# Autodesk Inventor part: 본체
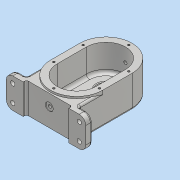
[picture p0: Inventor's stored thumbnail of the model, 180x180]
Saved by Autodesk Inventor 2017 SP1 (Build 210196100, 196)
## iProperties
Part Number: 본체
Material: 알루미늄 6061
Document SubType Name: Modeling
Designer: MRC
Density: 2.7 g/cm^3
Appearance: 알루미늄 - 평지
Mass: 756.449 g
Surface Area: 582.679 cm^2
Volume: 280.166 cm^3
Author: MRC
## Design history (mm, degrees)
sketch "스케치4"
  geometry: L1 (0, 0)-(0, -87); L2 (-40, 0)-(-40, -82); L3 (40, -82)-(40, 0); L4 (-40, -82)-(-61, -82); L5 (-61, -82)-(-61, -92); L6 (-61, -92)-(-35, -92); L7 (-35, -92)-(-35, -87); L8 (-35, -87)-(35, -87); L9 (35, -87)-(35, -92); L10 (35, -92)-(61, -92); L11 (61, -92)-(61, -82); L12 (61, -82)-(40, -82); A1 r 40 centre (0, 0) between (40, 0) and (-40, 0); 1 further point
  constraints: 26 end point, 7 perpendicular, 3 point on line, 2 midpoint, 2 point on circle, 2 tangent, 2 vertical, 1 centre point, 1 horizontal, 1 parallel
  dimensions: "d17" = 40 radius of A1; "d18" = 10 distance of L10.end L11.end; "d19" = 70 distance of L7.end L8.end; "d20" = 122 distance between parallel lines of L5 L11; "d21" = 61 distance from line of point (0, -43.5) L5; "d22" = 92 distance from line of L10 L1.start; "d23" = 5 distance of L8.end L9.end
extrude "돌출4" new body sketch "스케치4" distance "d24" = 46; taper "d25" = 0 deg
sketch "스케치5"
  geometry: L1 (0, 0)-(0, -45); L2 (-40, 0)-(-40, -45); L3 (40, -45)-(40, 0); A1 r 40 centre (0, 0) between (40, 0) and (-40, 0) reference; A2 r 40 centre (0, 0) between (40, 0) and (-40, 0); A3 r 40 centre (0, -45) between (-40, -45) and (40, -45); 1 further point
  constraints: 8 end point, 4 point on circle, 4 tangent, 2 centre point, 1 concentric, 1 midpoint, 1 parallel, 1 vertical
  dimensions: "d26" = 45 distance of L1.start L1.end
extrude "돌출5" join sketch "스케치5" distance "d27" = 3; taper "d28" = 0 deg
sketch "스케치6"
  geometry: L1 (0, 0)-(0, -45); L2 (-26, 0)-(-26, -45); L3 (26, -45)-(26, 0); A1 r 40 centre (0, 0) between (40, 0) and (-40, 0) reference; A2 r 26 centre (0, 0) between (26, 0) and (-26, 0); A3 r 26 centre (0, -45) between (-26, -45) and (26, -45); 1 further point
  constraints: 8 end point, 4 point on circle, 4 tangent, 2 centre point, 1 midpoint, 1 parallel, 1 vertical
  dimensions: "d29" = 26 radius of A2; "d30" = 45 distance of L1.start L1.end
extrude "돌출6" join sketch "스케치6" distance "d31" = 11; taper "d32" = 0 deg
sketch "스케치7"
  geometry: L1 (26, -45)-(26, 0) reference; L2 (-26, -45)-(-26, 0) reference; L3 (-26, -30)-(26, -30); A1 r 26 centre (0, 0) between (26, 0) and (-26, 0) reference
  constraints: 2 end point, 2 point on line, 1 perpendicular
  dimensions: "d33" = 30 distance from line of L3 A1.centre
extrude "돌출7" cut sketch "스케치7" distance "d34" = 3; taper "d35" = 0 deg
sketch "스케치8"
  geometry: L1 (0, 0)-(0, -45); L2 (-30, 0)-(-30, -45); L3 (30, -45)-(30, 0); A1 r 40 centre (0, -45) between (-40, -45) and (40, -45) reference; A2 r 40 centre (0, 0) between (40, 0) and (-40, 0) reference; A3 r 30 centre (0, 0) between (30, 0) and (-30, 0); A4 r 30 centre (0, -45) between (-30, -45) and (30, -45); 1 further point
  constraints: 8 end point, 4 point on circle, 4 tangent, 2 centre point, 1 midpoint, 1 parallel, 1 vertical
  dimensions: "d36" = 30 radius of A3
extrude "돌출8" cut sketch "스케치8" distance "d37" = 41; taper "d38" = 0 deg
hole "구멍1" diameter "d41" = 20; stored, may be unused: countersink angle "d45" = 90 deg, drill point angle "d47" = 0 deg; dims "d39" = 10, "d40" = 10, "d42" = 6, "d43" = 28, "d44" = 8, "d46" = 12
hole "구멍2" diameter "d50" = 22; stored, may be unused: countersink angle "d54" = 90 deg, drill point angle "d56" = 0 deg; dims "d48" = 10, "d49" = 10, "d51" = 6, "d52" = 28, "d53" = 8, "d55" = 100
sketch "스케치9"
  geometry: C1 r 11 at (0, 0) reference; C2 r 14 at (0, 0); A1 r 26 centre (0, 0) between (26, 0) and (-26, 0) reference
  constraints: 1 centre point, 1 coincident
  dimensions: "d57" = 28 diameter of C2
extrude "돌출9" cut sketch "스케치9" distance "d58" = 4; taper "d59" = 0 deg
fillet "모깎기4" dims "d60" = 10, "d61" = 5
sketch "스케치10"
  geometry: L1 (-101, 36)-(-101, 10) reference; L2 (-80, 0)-(-91, 0) reference; L3 (-80, 46)-(-80, 0) reference; L4 (-80, 46)-(-91, 46) reference; A1 r 10 centre (11, 36) between (21, 36) and (11, 46) reference; A2 r 10 centre (11, 10) between (11, 0) and (21, 10) reference; A3 r 10 centre (-91, 36) between (-91, 46) and (-101, 36) reference; A4 r 10 centre (-91, 10) between (-101, 10) and (-91, 0) reference; 1 further point
hole "구멍3" sketch "스케치10" at (-91, 10), (11, 36), (11, 10), (-91, 36) diameter "d62" = 6.6; stored, may be unused: countersink angle "d66" = 90 deg, drill point angle "d68" = 0 deg; dims "d63" = 6, "d64" = 11, "d65" = 2, "d67" = 10
node "작업 평면1"
sketch "스케치11"
  geometry: L1 (75, 49)-(-5, 49) reference; C1 r 6 at (35, 28); 1 further point
  constraints: 1 centre point, 1 vertical alignment
  dimensions: "d70" = 12 diameter of C1; "d71" = 21 distance from line of L1 C1.centre
extrude "돌출10" join sketch "스케치11" stored distance "d72" = 4; taper "d73" = 0 deg
hole "구멍4" diameter "d76" = 4.917; stored, may be unused: countersink angle "d80" = 90 deg, drill point angle "d82" = 0 deg; dims "d74" = 10, "d75" = 10, "d77" = 12, "d78" = 11, "d79" = 2, "d81" = 17.1
sketch "스케치12"
  geometry: L1 (0, 0)-(70, 0) reference; L2 (75, 49)-(-5, 49) reference; 3 further points
  constraints: 1 midpoint, 1 vertical alignment
  dimensions: "d83" = 21 distance from line of point (35, 28) L2
hole "구멍5" sketch "스케치12" at (35, 28) diameter "d84" = 4.917; stored, may be unused: countersink angle "d88" = 90 deg, drill point angle "d90" = 0 deg; dims "d85" = 12, "d86" = 12, "d87" = 1, "d89" = 17.1
sketch "스케치13"
  geometry: C1 r 14 at (0, 0) reference; 1 further point
  constraints: 1 vertical alignment
  dimensions: "d91" = 20 distance of C1.centre point (0, 20)
hole "구멍6" sketch "스케치13" at (0, 20) diameter "d92" = 3.242; stored, may be unused: countersink angle "d96" = 90 deg, drill point angle "d98" = 118 deg; dims "d93" = 8, "d94" = 12, "d95" = 1, "d97" = 10
sketch "스케치14"
  geometry: A1 r 30 centre (0, 0) between (30, 0) and (-30, 0) reference; 1 further point
  constraints: 1 vertical alignment
  dimensions: "d102" = 35 distance of A1.centre point (0, 35)
hole "구멍7" sketch "스케치14" at (0, 35) diameter "d103" = 3.242; stored, may be unused: countersink angle "d107" = 90 deg, drill point angle "d109" = 118 deg; dims "d104" = 8, "d105" = 12, "d106" = 1, "d108" = 10
sketch "스케치15"
  geometry: L1 (0, 0)-(0, -45); L2 (-35, 0)-(-35, -45); L3 (35, -45)-(35, 0); A1 r 40 centre (0, -45) between (-40, -45) and (40, -45) reference; A2 r 40 centre (0, 0) between (40, 0) and (-40, 0) reference; A3 r 35 centre (0, 0) between (35, 0) and (-35, 0); A4 r 35 centre (0, -45) between (-35, -45) and (35, -45); 6 further points
  constraints: 8 end point, 5 point on circle, 4 coincident, 4 tangent, 2 centre point, 1 midpoint, 1 parallel, 1 vertical
  dimensions: "d110" = 70 diameter of A4
hole "구멍8" sketch "스케치15" at (-35, 0), (35, 0), (35, -45), (-35, -45), (0, -80) diameter "d111" = 3.242; stored, may be unused: countersink angle "d115" = 90 deg, drill point angle "d117" = 118 deg; dims "d112" = 8, "d113" = 12, "d114" = 1, "d116" = 10
fillet "모깎기5" dims "d118" = 0.3
chamfer "모따기1" distance "d119" = 1; stored, may be unused: second distance "d120" = 2, angle "d121" = 45 deg
fillet "모깎기6" dims "d122" = 3
sketch "스케치16" dims "d26" = 45
  geometry: L1 (32, -87)-(-32, -87) reference; L2 (-51, -92)-(-61, -92) reference; 2 further points
  constraints: 1 midpoint, 1 vertical alignment, 1 other
  dimensions: "d123" = 12 distance from line of point (0, -80) L2
feature "엠보싱1" sketch "스케치16" dims "d17" = 40, "d18" = 10, "d19" = 70, "d20" = 122, "d21" = 61, "d22" = 92, "d23" = 5, "d26" = 45, "d124" = 0.5, "d125" = 0
fillet "모깎기7" dims "d126" = 3
node "솔리드2"
pattern_circular "원형 패턴1" dims angle "d100" = 360 deg
node "투영된 루프1"
